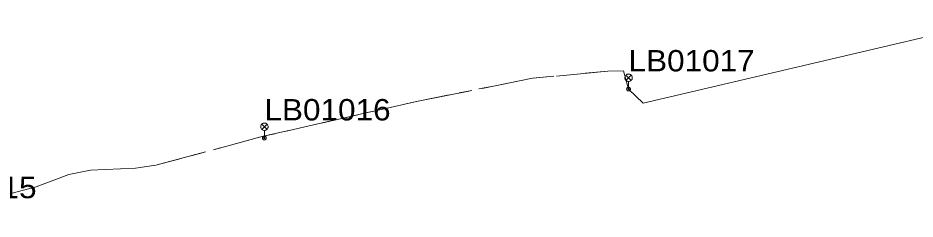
# Model space of a CAD drawing. Extents: x -688049 to -687261, y -973611 to -973038.
# Drawn here: x -687519.3 to -687428.6, y -973238.9 to -973218.5 of the extents above; entities that cross this region are included whole.
import ezdxf

# ---------------------------------------------------------------- set-up
doc = ezdxf.new("R2010")
doc.units = 0
doc.header["$LTSCALE"] = 0.87
doc.linetypes.add('LONG_DASH_SHORT_DASH', pattern=[9.9, 6, -1.2, 1.5, -1.2])
doc.layers.add('1', color=7, linetype='Continuous', lineweight=13)

msp = doc.modelspace()

# ---------------------------------------------------------------- linework, layer by layer
at = {"layer": '1'}
for p, q in [((-687457.815, -973224.335), (-687457.285, -973224.865)), ((-687457.815, -973224.865), (-687457.285, -973224.335)), ((-687494.645, -973229.295), (-687494.115, -973229.825)), ((-687494.645, -973229.825), (-687494.115, -973229.295)), ((-687494.38, -973230.71), (-687494.38, -973229.935))]:
    msp.add_line(p, q, dxfattribs=at)
at = {"layer": '1', "linetype": 'LONG_DASH_SHORT_DASH'}
for q in [(-687491.9, -973229.94), (-687491.9, -973229.94), (-687491.9, -973229.94), (-687494.38, -973230.71), (-687494.38, -973230.71)]:
    msp.add_line((-687494.49, -973230.53), q, dxfattribs=at)
at = {"layer": '1'}
msp.add_lwpolyline([(-687420.016, -973218.543), (-687420.383, -973218.795), (-687456.084, -973227.179), (-687457.55, -973225.75), (-687457.55, -973224.975)], dxfattribs=at)
at = {"layer": '1', "linetype": 'LONG_DASH_SHORT_DASH'}
for points in [[(-687457.55, -973225.75), (-687458.05, -973223.91), (-687459.63, -973223.94), (-687467.25, -973224.65), (-687478.82, -973226.97), (-687494.49, -973230.53)], [(-687457.55, -973225.75), (-687458.05, -973223.91), (-687459.63, -973223.94), (-687467.25, -973224.65), (-687478.82, -973226.97), (-687494.49, -973230.53)], [(-687457.55, -973225.75), (-687458.05, -973223.91), (-687459.63, -973223.94), (-687467.25, -973224.65), (-687478.82, -973226.97), (-687494.49, -973230.53), (-687491.9, -973229.94)], [(-687457.55, -973225.75), (-687458.05, -973223.91), (-687459.63, -973223.94), (-687467.25, -973224.65), (-687478.82, -973226.97), (-687494.49, -973230.53)], [(-687488.6, -973229.19), (-687478.82, -973226.97), (-687467.25, -973224.65), (-687465.12, -973224.45)], [(-687488.6, -973229.19), (-687478.82, -973226.97), (-687467.25, -973224.65), (-687465.12, -973224.45)], [(-687488.6, -973229.19), (-687478.82, -973226.97), (-687467.25, -973224.65), (-687465.12, -973224.45)], [(-687488.6, -973229.19), (-687478.82, -973226.97), (-687467.25, -973224.65), (-687465.12, -973224.45)], [(-687461.92, -973224.15), (-687459.63, -973223.94), (-687458.05, -973223.91), (-687457.55, -973225.75)], [(-687461.92, -973224.15), (-687459.63, -973223.94), (-687458.05, -973223.91), (-687457.55, -973225.75)], [(-687461.92, -973224.15), (-687459.63, -973223.94), (-687458.05, -973223.91), (-687457.55, -973225.75)], [(-687461.92, -973224.15), (-687459.63, -973223.94), (-687458.05, -973223.91), (-687457.55, -973225.75)], [(-687494.49, -973230.53), (-687505.37, -973233.46), (-687507.43, -973233.77), (-687511.98, -973233.97), (-687514.17, -973234.4), (-687517.46, -973235.64), (-687530.07, -973238.91)], [(-687494.49, -973230.53), (-687505.37, -973233.46), (-687507.43, -973233.77), (-687511.98, -973233.97), (-687514.17, -973234.4), (-687517.46, -973235.64), (-687530.07, -973238.91)], [(-687494.49, -973230.53), (-687505.37, -973233.46), (-687507.43, -973233.77), (-687511.98, -973233.97), (-687514.17, -973234.4), (-687517.46, -973235.64), (-687530.07, -973238.91)], [(-687494.49, -973230.53), (-687505.37, -973233.46), (-687507.43, -973233.77), (-687511.98, -973233.97), (-687514.17, -973234.4), (-687517.46, -973235.64), (-687530.07, -973238.91)], [(-687517.82, -973235.73), (-687517.46, -973235.64), (-687514.17, -973234.4), (-687511.98, -973233.97), (-687507.43, -973233.77), (-687505.37, -973233.46), (-687494.49, -973230.53)], [(-687517.82, -973235.73), (-687517.46, -973235.64), (-687514.17, -973234.4), (-687511.98, -973233.97), (-687507.43, -973233.77), (-687505.37, -973233.46), (-687494.49, -973230.53), (-687494.38, -973230.71)], [(-687517.82, -973235.73), (-687517.46, -973235.64), (-687514.17, -973234.4), (-687511.98, -973233.97), (-687507.43, -973233.77), (-687505.37, -973233.46), (-687494.49, -973230.53)], [(-687517.82, -973235.73), (-687517.46, -973235.64), (-687514.17, -973234.4), (-687511.98, -973233.97), (-687507.43, -973233.77), (-687505.37, -973233.46), (-687494.49, -973230.53), (-687494.38, -973230.71)]]:
    msp.add_lwpolyline(points, dxfattribs=at)
at = {"layer": '1'}
for points in [[(-687457.175, -973224.6), (-687457.181, -973224.535), (-687457.198, -973224.472), (-687457.225, -973224.413), (-687457.263, -973224.359), (-687457.309, -973224.313), (-687457.362, -973224.275), (-687457.422, -973224.248), (-687457.485, -973224.231), (-687457.55, -973224.225), (-687457.615, -973224.231), (-687457.678, -973224.248), (-687457.738, -973224.275), (-687457.791, -973224.313), (-687457.837, -973224.359), (-687457.875, -973224.413), (-687457.902, -973224.472), (-687457.919, -973224.535), (-687457.925, -973224.6), (-687457.919, -973224.665), (-687457.902, -973224.728), (-687457.875, -973224.788), (-687457.837, -973224.841), (-687457.791, -973224.887), (-687457.738, -973224.925), (-687457.678, -973224.952), (-687457.615, -973224.969), (-687457.55, -973224.975), (-687457.485, -973224.969), (-687457.422, -973224.952), (-687457.362, -973224.925), (-687457.309, -973224.887), (-687457.263, -973224.841), (-687457.225, -973224.788), (-687457.198, -973224.728), (-687457.181, -973224.665)], [(-687457.36, -973225.75), (-687457.363, -973225.717), (-687457.371, -973225.685), (-687457.385, -973225.655), (-687457.404, -973225.628), (-687457.428, -973225.604), (-687457.455, -973225.585), (-687457.485, -973225.571), (-687457.517, -973225.563), (-687457.55, -973225.56), (-687457.583, -973225.563), (-687457.615, -973225.571), (-687457.645, -973225.585), (-687457.672, -973225.604), (-687457.696, -973225.628), (-687457.715, -973225.655), (-687457.729, -973225.685), (-687457.737, -973225.717), (-687457.74, -973225.75), (-687457.737, -973225.783), (-687457.729, -973225.815), (-687457.715, -973225.845), (-687457.696, -973225.872), (-687457.672, -973225.896), (-687457.645, -973225.915), (-687457.615, -973225.929), (-687457.583, -973225.937), (-687457.55, -973225.94), (-687457.517, -973225.937), (-687457.485, -973225.929), (-687457.455, -973225.915), (-687457.428, -973225.896), (-687457.404, -973225.872), (-687457.385, -973225.845), (-687457.371, -973225.815), (-687457.363, -973225.783)], [(-687457.5, -973225.75), (-687457.501, -973225.741), (-687457.503, -973225.733), (-687457.507, -973225.725), (-687457.512, -973225.718), (-687457.518, -973225.712), (-687457.525, -973225.707), (-687457.533, -973225.703), (-687457.541, -973225.701), (-687457.55, -973225.7), (-687457.559, -973225.701), (-687457.567, -973225.703), (-687457.575, -973225.707), (-687457.582, -973225.712), (-687457.588, -973225.718), (-687457.593, -973225.725), (-687457.597, -973225.733), (-687457.599, -973225.741), (-687457.6, -973225.75), (-687457.599, -973225.759), (-687457.597, -973225.767), (-687457.593, -973225.775), (-687457.588, -973225.782), (-687457.582, -973225.788), (-687457.575, -973225.793), (-687457.567, -973225.797), (-687457.559, -973225.799), (-687457.55, -973225.8), (-687457.541, -973225.799), (-687457.533, -973225.797), (-687457.525, -973225.793), (-687457.518, -973225.788), (-687457.512, -973225.782), (-687457.507, -973225.775), (-687457.503, -973225.767), (-687457.501, -973225.759)], [(-687494.005, -973229.56), (-687494.011, -973229.495), (-687494.028, -973229.432), (-687494.055, -973229.372), (-687494.093, -973229.319), (-687494.139, -973229.273), (-687494.192, -973229.235), (-687494.252, -973229.208), (-687494.315, -973229.191), (-687494.38, -973229.185), (-687494.445, -973229.191), (-687494.508, -973229.208), (-687494.568, -973229.235), (-687494.621, -973229.273), (-687494.667, -973229.319), (-687494.705, -973229.372), (-687494.732, -973229.432), (-687494.749, -973229.495), (-687494.755, -973229.56), (-687494.749, -973229.625), (-687494.732, -973229.688), (-687494.705, -973229.747), (-687494.667, -973229.801), (-687494.621, -973229.847), (-687494.568, -973229.885), (-687494.508, -973229.912), (-687494.445, -973229.929), (-687494.38, -973229.935), (-687494.315, -973229.929), (-687494.252, -973229.912), (-687494.192, -973229.885), (-687494.139, -973229.847), (-687494.093, -973229.801), (-687494.055, -973229.747), (-687494.028, -973229.688), (-687494.011, -973229.625)], [(-687494.19, -973230.71), (-687494.193, -973230.677), (-687494.201, -973230.645), (-687494.215, -973230.615), (-687494.234, -973230.588), (-687494.258, -973230.564), (-687494.285, -973230.545), (-687494.315, -973230.531), (-687494.347, -973230.523), (-687494.38, -973230.52), (-687494.413, -973230.523), (-687494.445, -973230.531), (-687494.475, -973230.545), (-687494.502, -973230.564), (-687494.526, -973230.588), (-687494.545, -973230.615), (-687494.559, -973230.645), (-687494.567, -973230.677), (-687494.57, -973230.71), (-687494.567, -973230.743), (-687494.559, -973230.775), (-687494.545, -973230.805), (-687494.526, -973230.832), (-687494.502, -973230.856), (-687494.475, -973230.875), (-687494.445, -973230.889), (-687494.413, -973230.897), (-687494.38, -973230.9), (-687494.347, -973230.897), (-687494.315, -973230.889), (-687494.285, -973230.875), (-687494.258, -973230.856), (-687494.234, -973230.832), (-687494.215, -973230.805), (-687494.201, -973230.775), (-687494.193, -973230.743)], [(-687494.33, -973230.71), (-687494.331, -973230.701), (-687494.333, -973230.693), (-687494.337, -973230.685), (-687494.342, -973230.678), (-687494.348, -973230.672), (-687494.355, -973230.667), (-687494.363, -973230.663), (-687494.371, -973230.661), (-687494.38, -973230.66), (-687494.389, -973230.661), (-687494.397, -973230.663), (-687494.405, -973230.667), (-687494.412, -973230.672), (-687494.418, -973230.678), (-687494.423, -973230.685), (-687494.427, -973230.693), (-687494.429, -973230.701), (-687494.43, -973230.71), (-687494.429, -973230.719), (-687494.427, -973230.727), (-687494.423, -973230.735), (-687494.418, -973230.742), (-687494.412, -973230.748), (-687494.405, -973230.753), (-687494.397, -973230.757), (-687494.389, -973230.759), (-687494.38, -973230.76), (-687494.371, -973230.759), (-687494.363, -973230.757), (-687494.355, -973230.753), (-687494.348, -973230.748), (-687494.342, -973230.742), (-687494.337, -973230.735), (-687494.333, -973230.727), (-687494.331, -973230.719)]]:
    msp.add_lwpolyline(points, close=True, dxfattribs=at)

# ---------------------------------------------------------------- texts
at = {"layer": '1', "width": 1.1}
for s, p in [('LB01017', (-687457.55, -973223.962)), ('LB01016', (-687494.38, -973228.922)), ('LB01015', (-687530.19, -973236.797))]:
    msp.add_text(s, height=2.167, dxfattribs=at).set_placement(p)

doc.saveas('drawing.dxf')
